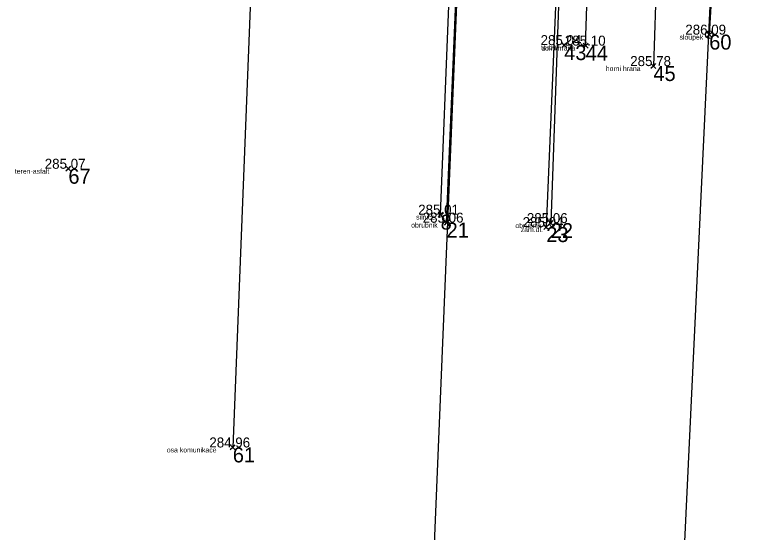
# Model space of a CAD drawing. Extents: x -456675 to -456278, y -1112395 to -1112217.
# Drawn here: x -456327.23 to -456312.2, y -1112322.8 to -1112312.43 of the extents above; entities that cross this region are included whole.
import ezdxf

# ---------------------------------------------------------------- set-up
doc = ezdxf.new("R2010")
doc.units = 0
for name, color, linetype in [('Cislo_bodu', 7, 'Continuous'), ('g_chodniky', 7, 'Continuous'), ('g_komunikace', 7, 'Continuous'), ('g_obrubnik', 7, 'Continuous'), ('g_ploty', 7, 'Continuous'), ('g_terenni_hrany', 7, 'Continuous'), ('Katastralni_mapa', 7, 'Continuous'), ('Kod_bodu', 7, 'Continuous'), ('Vyska_bodu', 7, 'Continuous'), ('Znacka_bodu', 7, 'Continuous')]:
    doc.layers.add(name, color=color, linetype=linetype)

msp = doc.modelspace()

# ---------------------------------------------------------------- linework, layer by layer
at = {"layer": 'g_chodniky'}
msp.add_lwpolyline([(-456316.013, -1112302.67), (-456316.313, -1112310.52), (-456316.573, -1112316.68)], dxfattribs=at)
at = {"layer": 'g_komunikace'}
for points in [[(-456321.503, -1112286.87), (-456321.723, -1112292.24), (-456322.153, -1112302.79), (-456322.503, -1112311.93), (-456322.863, -1112321.1)], [(-456318.693, -1112316.43), (-456318.363, -1112308.05), (-456318.163, -1112303.65), (-456318.053, -1112300.62), (-456317.813, -1112294.62), (-456317.613, -1112289.62)]]:
    msp.add_lwpolyline(points, dxfattribs=at)
at = {"layer": 'g_obrubnik'}
for points in [[(-456315.393, -1112289.05), (-456315.693, -1112296.16), (-456315.933, -1112302.15), (-456316.253, -1112310.15), (-456316.483, -1112316.6)], [(-456318.573, -1112316.59), (-456318.283, -1112309.61), (-456318.073, -1112304.61), (-456318.043, -1112303.64), (-456317.923, -1112300.63), (-456317.883, -1112299.65), (-456317.673, -1112294.65), (-456317.473, -1112289.63)]]:
    msp.add_lwpolyline(points, dxfattribs=at)
at = {"layer": 'g_ploty'}
msp.add_lwpolyline([(-456312.263, -1112289.35), (-456312.683, -1112299.42), (-456312.803, -1112302.81), (-456313.013, -1112306.04), (-456313.103, -1112309.4), (-456313.303, -1112312.82)], dxfattribs=at)
msp.add_circle((-456313.303, -1112312.82), 0.075, dxfattribs=at)
at = {"layer": 'g_terenni_hrany'}
for points in [[(-456315.783, -1112313.04), (-456315.423, -1112302.36), (-456315.273, -1112294.59)], [(-456314.043, -1112294.61), (-456314.123, -1112304.22), (-456314.423, -1112313.45)]]:
    msp.add_lwpolyline(points, dxfattribs=at)
at = {"layer": 'Katastralni_mapa'}
for points in [[(-456315.703, -1112247.69), (-456320.023, -1112351.98)], [(-456314.273, -1112333.16), (-456312.203, -1112289.34)]]:
    msp.add_lwpolyline(points, dxfattribs=at)
at = {"layer": 'Znacka_bodu'}
for p, q in [((-456313.303, -1112312.82), (-456313.353, -1112312.77)), ((-456313.303, -1112312.82), (-456313.353, -1112312.87)), ((-456313.303, -1112312.82), (-456313.253, -1112312.77)), ((-456313.303, -1112312.82), (-456313.253, -1112312.87)), ((-456316.213, -1112313.03), (-456316.263, -1112312.98)), ((-456316.213, -1112313.03), (-456316.163, -1112312.98)), ((-456316.213, -1112313.03), (-456316.263, -1112313.08)), ((-456316.213, -1112313.03), (-456316.163, -1112313.08)), ((-456315.783, -1112313.04), (-456315.833, -1112312.99)), ((-456315.783, -1112313.04), (-456315.833, -1112313.09)), ((-456315.783, -1112313.04), (-456315.733, -1112312.99)), ((-456315.783, -1112313.04), (-456315.733, -1112313.09)), ((-456314.423, -1112313.45), (-456314.473, -1112313.4)), ((-456314.423, -1112313.45), (-456314.373, -1112313.4)), ((-456314.423, -1112313.45), (-456314.473, -1112313.5)), ((-456314.423, -1112313.45), (-456314.373, -1112313.5)), ((-456326.163, -1112315.51), (-456326.213, -1112315.46)), ((-456326.163, -1112315.51), (-456326.213, -1112315.56)), ((-456326.163, -1112315.51), (-456326.113, -1112315.46)), ((-456326.163, -1112315.51), (-456326.113, -1112315.56)), ((-456318.693, -1112316.43), (-456318.743, -1112316.38)), ((-456318.693, -1112316.43), (-456318.743, -1112316.48)), ((-456318.693, -1112316.43), (-456318.643, -1112316.38)), ((-456318.693, -1112316.43), (-456318.643, -1112316.48)), ((-456318.573, -1112316.59), (-456318.623, -1112316.54)), ((-456318.573, -1112316.59), (-456318.523, -1112316.54)), ((-456316.483, -1112316.6), (-456316.533, -1112316.55)), ((-456316.483, -1112316.6), (-456316.433, -1112316.55)), ((-456318.573, -1112316.59), (-456318.623, -1112316.64)), ((-456318.573, -1112316.59), (-456318.523, -1112316.64)), ((-456316.573, -1112316.68), (-456316.623, -1112316.63)), ((-456316.573, -1112316.68), (-456316.623, -1112316.73)), ((-456316.573, -1112316.68), (-456316.523, -1112316.63)), ((-456316.573, -1112316.68), (-456316.523, -1112316.73)), ((-456316.483, -1112316.6), (-456316.533, -1112316.65)), ((-456316.483, -1112316.6), (-456316.433, -1112316.65)), ((-456322.863, -1112321.1), (-456322.913, -1112321.05)), ((-456322.863, -1112321.1), (-456322.813, -1112321.05)), ((-456322.863, -1112321.1), (-456322.913, -1112321.15)), ((-456322.863, -1112321.1), (-456322.813, -1112321.15))]:
    msp.add_line(p, q, dxfattribs=at)

# ---------------------------------------------------------------- texts
at = {"layer": 'Cislo_bodu'}
for s, p in [('60', (-456313.303, -1112313.12)), ('43', (-456316.213, -1112313.33)), ('44', (-456315.783, -1112313.34)), ('45', (-456314.423, -1112313.75)), ('67', (-456326.163, -1112315.81)), ('8', (-456318.693, -1112316.73)), ('21', (-456318.573, -1112316.89)), ('23', (-456316.573, -1112316.98)), ('22', (-456316.483, -1112316.9)), ('61', (-456322.863, -1112321.4))]:
    msp.add_text(s, height=0.3, dxfattribs=at).set_placement(p)
at = {"layer": 'Kod_bodu'}
for s, p in [('sloupek', (-456313.899, -1112312.92)), ('teren', (-456316.679, -1112313.13)), ('dolni hrana', (-456316.674, -1112313.14)), ('horni hrana', (-456315.379, -1112313.55)), ('teren-asfalt', (-456327.237, -1112315.61)), ('silnice', (-456319.184, -1112316.53)), ('obrubnik', (-456319.284, -1112316.69)), ('obrubnik', (-456317.194, -1112316.7)), ('zam.dl.', (-456317.085, -1112316.78)), ('osa komunikace', (-456324.188, -1112321.2))]:
    msp.add_text(s, height=0.1, dxfattribs=at).set_placement(p)
at = {"layer": 'Vyska_bodu'}
for s, p in [('286.09', (-456313.783, -1112312.82)), ('285.04', (-456316.687, -1112313.03)), ('285.10', (-456316.2, -1112313.04)), ('285.78', (-456314.888, -1112313.45)), ('285.07', (-456326.637, -1112315.51)), ('285.01', (-456319.143, -1112316.43)), ('285.06', (-456319.052, -1112316.59)), ('285.06', (-456316.962, -1112316.6)), ('285.04', (-456317.047, -1112316.68)), ('284.96', (-456323.334, -1112321.1))]:
    msp.add_text(s, height=0.2, dxfattribs=at).set_placement(p)

doc.saveas('drawing.dxf')
